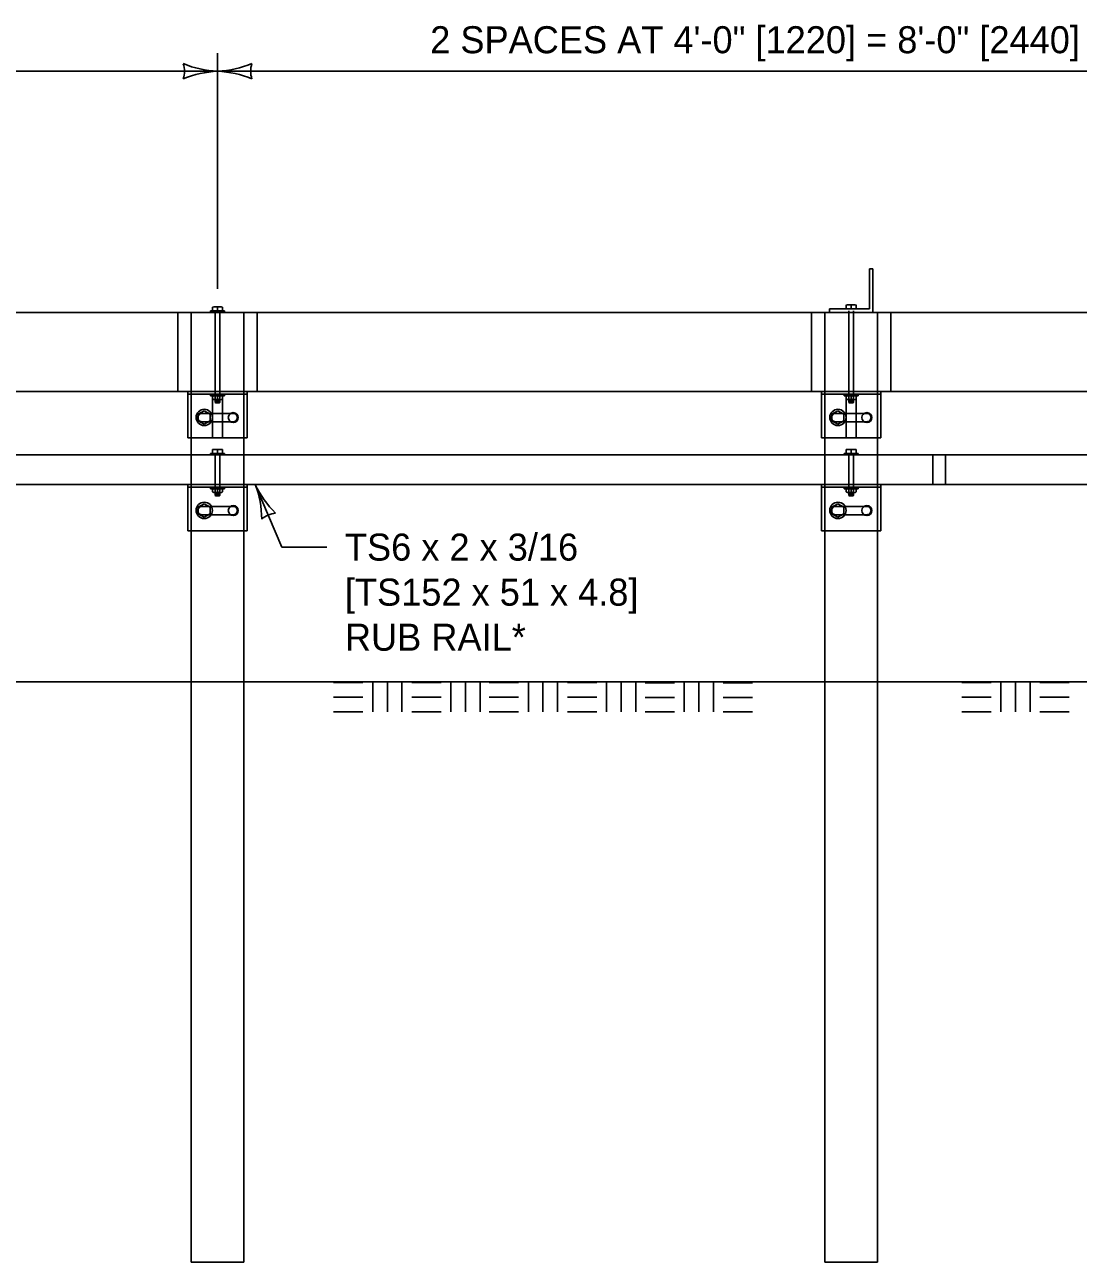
# Model space of a CAD drawing. Extents: x 49983 to 50021, y 49963.5 to 50011.4.
# Drawn here: x 50007.107 to 50009.444, y 49993.178 to 49995.925 of the extents above; entities that cross this region are included whole.
import ezdxf

# ---------------------------------------------------------------- set-up
doc = ezdxf.new("R2010")
doc.units = 0
for name, color, linetype in [('Level 1', 7, 'Continuous'), ('Level 10', 7, 'Continuous'), ('Level 2', 7, 'Continuous'), ('Level 3', 7, 'Continuous'), ('Level 4', 7, 'Continuous')]:
    doc.layers.add(name, color=color, linetype=linetype)

msp = doc.modelspace()

# ---------------------------------------------------------------- linework, layer by layer
at = {"layer": 'Level 1'}
for p, q in [((50008.9809, 49995.2944), (50008.9809, 49995.3826)), ((50008.9809, 49995.3826), (50008.9888, 49995.3826)), ((50008.9888, 49995.3826), (50008.9888, 49995.2862)), ((50008.9296, 49995.3027), (50008.9296, 49995.2944)), ((50008.9351, 49995.3033), (50008.9461, 49995.3033)), ((50008.9406, 49995.3027), (50008.9406, 49995.2944)), ((50008.9516, 49995.3027), (50008.9516, 49995.2944)), ((50013.5013, 49995.2862), (50005.468, 49995.2862)), ((50007.4765, 49995.2862), (50007.6522, 49995.2862)), ((50007.622, 49995.2862), (50007.5067, 49995.2862)), ((50007.5193, 49995.2899), (50007.5506, 49995.2899)), ((50007.5193, 49995.2899), (50007.5193, 49995.2862)), ((50007.524, 49995.2981), (50007.524, 49995.2899)), ((50007.5295, 49995.2988), (50007.5405, 49995.2988)), ((50007.535, 49995.2981), (50007.535, 49995.2899)), ((50007.5461, 49995.2981), (50007.5461, 49995.2899)), ((50007.5506, 49995.2899), (50007.5506, 49995.2862)), ((50008.882, 49995.2862), (50009.0577, 49995.2862)), ((50008.8924, 49995.2865), (50008.8924, 49995.2944)), ((50008.8924, 49995.2944), (50008.9809, 49995.2944)), ((50009.0275, 49995.2862), (50008.9123, 49995.2862)), ((50013.5013, 49995.1105), (50005.468, 49995.1105)), ((50007.4692, 49995.008), (50007.4692, 49995.1105)), ((50007.4765, 49995.1105), (50007.6522, 49995.1105)), ((50007.5204, 49995.1105), (50007.6522, 49995.1105)), ((50007.6009, 49995.008), (50007.6009, 49995.1105)), ((50008.8747, 49995.008), (50008.8747, 49995.1105)), ((50008.882, 49995.1105), (50009.0577, 49995.1105)), ((50008.926, 49995.1105), (50009.0577, 49995.1105)), ((50009.0065, 49995.008), (50009.0065, 49995.1105)), ((50007.6009, 49995.105), (50007.4692, 49995.105)), ((50007.5193, 49995.1014), (50007.5193, 49995.1051)), ((50007.5193, 49995.1014), (50007.5507, 49995.1014)), ((50007.524, 49995.0942), (50007.524, 49995.0997)), ((50007.5241, 49995.1014), (50007.5241, 49995.0998)), ((50007.5241, 49995.008), (50007.5241, 49995.0941)), ((50007.5295, 49995.0925), (50007.5406, 49995.0925)), ((50007.5299, 49995.0864), (50007.5299, 49995.0925)), ((50007.5402, 49995.0864), (50007.5299, 49995.0864)), ((50007.5299, 49995.0864), (50007.531, 49995.0853)), ((50007.531, 49995.0853), (50007.5392, 49995.0853)), ((50007.5314, 49995.091), (50007.5387, 49995.091)), ((50007.5314, 49995.09), (50007.5387, 49995.09)), ((50007.5314, 49995.089), (50007.5387, 49995.089)), ((50007.5314, 49995.0879), (50007.5387, 49995.0879)), ((50007.5351, 49995.0997), (50007.5351, 49995.0942)), ((50007.5402, 49995.0864), (50007.5392, 49995.0853)), ((50007.5402, 49995.0864), (50007.5402, 49995.0925)), ((50007.546, 49995.1014), (50007.546, 49995.0998)), ((50007.546, 49995.008), (50007.546, 49995.0941)), ((50007.5462, 49995.0942), (50007.5462, 49995.0997)), ((50007.5507, 49995.1014), (50007.5507, 49995.1051)), ((50009.0065, 49995.105), (50008.8747, 49995.105)), ((50008.9248, 49995.1014), (50008.9248, 49995.1051)), ((50008.9248, 49995.1014), (50008.9562, 49995.1014)), ((50008.9295, 49995.0942), (50008.9295, 49995.0997)), ((50008.9296, 49995.1014), (50008.9296, 49995.0998)), ((50008.9296, 49995.008), (50008.9296, 49995.0941)), ((50008.9351, 49995.0925), (50008.9462, 49995.0925)), ((50008.9355, 49995.0864), (50008.9355, 49995.0925)), ((50008.9458, 49995.0864), (50008.9355, 49995.0864)), ((50008.9355, 49995.0864), (50008.9365, 49995.0853)), ((50008.9365, 49995.0853), (50008.9447, 49995.0853)), ((50008.937, 49995.091), (50008.9442, 49995.091)), ((50008.937, 49995.09), (50008.9442, 49995.09)), ((50008.937, 49995.089), (50008.9442, 49995.089)), ((50008.937, 49995.0879), (50008.9442, 49995.0879)), ((50008.9406, 49995.0997), (50008.9406, 49995.0942)), ((50008.9458, 49995.0864), (50008.9447, 49995.0853)), ((50008.9458, 49995.0864), (50008.9458, 49995.0925)), ((50008.9516, 49995.1014), (50008.9516, 49995.0998)), ((50008.9516, 49995.008), (50008.9516, 49995.0941)), ((50008.9517, 49995.0942), (50008.9517, 49995.0997)), ((50008.9562, 49995.1014), (50008.9562, 49995.1051)), ((50007.5055, 49995.0678), (50007.4923, 49995.0601)), ((50007.4923, 49995.0601), (50007.4923, 49995.0453)), ((50007.5186, 49995.0601), (50007.5055, 49995.0678)), ((50007.5186, 49995.0453), (50007.5186, 49995.0601)), ((50007.5214, 49995.062), (50007.5241, 49995.062)), ((50007.546, 49995.062), (50007.5693, 49995.062)), ((50008.911, 49995.0678), (50008.8979, 49995.0601)), ((50008.8979, 49995.0601), (50008.8979, 49995.0453)), ((50008.9241, 49995.0601), (50008.911, 49995.0678)), ((50008.9241, 49995.0453), (50008.9241, 49995.0601)), ((50008.9269, 49995.062), (50008.9296, 49995.062)), ((50008.9516, 49995.062), (50008.9749, 49995.062)), ((50007.4923, 49995.0453), (50007.5055, 49995.0382)), ((50007.5055, 49995.0382), (50007.5186, 49995.0453)), ((50007.521, 49995.0437), (50007.5241, 49995.0437)), ((50007.546, 49995.0437), (50007.5698, 49995.0437)), ((50008.8979, 49995.0453), (50008.911, 49995.0382)), ((50008.911, 49995.0382), (50008.9241, 49995.0453)), ((50008.9266, 49995.0437), (50008.9296, 49995.0437)), ((50008.9516, 49995.0437), (50008.9754, 49995.0437)), ((50007.6009, 49995.008), (50007.4692, 49995.008)), ((50007.4763, 49995.008), (50007.4763, 49994.9698)), ((50007.5935, 49995.008), (50007.5935, 49994.9698)), ((50009.0065, 49995.008), (50008.8747, 49995.008)), ((50008.8819, 49995.008), (50008.8819, 49994.9698)), ((50008.999, 49995.008), (50008.999, 49994.9698)), ((50007.5193, 49994.9734), (50007.5506, 49994.9734)), ((50007.5193, 49994.9734), (50007.5193, 49994.9698)), ((50007.524, 49994.9817), (50007.524, 49994.9734)), ((50007.5295, 49994.9823), (50007.5405, 49994.9823)), ((50007.535, 49994.9817), (50007.535, 49994.9734)), ((50007.5461, 49994.9817), (50007.5461, 49994.9734)), ((50007.5506, 49994.9734), (50007.5506, 49994.9698)), ((50008.9249, 49994.9734), (50008.9561, 49994.9734)), ((50008.9249, 49994.9734), (50008.9249, 49994.9698)), ((50008.9296, 49994.9817), (50008.9296, 49994.9734)), ((50008.9351, 49994.9823), (50008.9461, 49994.9823)), ((50008.9406, 49994.9817), (50008.9406, 49994.9734)), ((50008.9516, 49994.9817), (50008.9516, 49994.9734)), ((50008.9561, 49994.9734), (50008.9561, 49994.9698)), ((50010.2874, 49994.9698), (50004.5699, 49994.9698)), ((50009.1498, 49994.9698), (50009.1498, 49994.9041)), ((50010.287, 49994.9041), (50005.1444, 49994.9041)), ((50007.4692, 49994.8016), (50007.4692, 49994.9041)), ((50007.6009, 49994.8986), (50007.4692, 49994.8986)), ((50007.6516, 49994.9041), (50007.4759, 49994.9041)), ((50007.5193, 49994.8949), (50007.5193, 49994.8986)), ((50007.5193, 49994.8949), (50007.5507, 49994.8949)), ((50007.5199, 49994.9041), (50007.6516, 49994.9041)), ((50007.524, 49994.8876), (50007.524, 49994.8932)), ((50007.5351, 49994.8932), (50007.5351, 49994.8876)), ((50007.5462, 49994.8876), (50007.5462, 49994.8932)), ((50007.5507, 49994.8949), (50007.5507, 49994.8986)), ((50007.6009, 49994.8016), (50007.6009, 49994.9041)), ((50008.8747, 49994.8016), (50008.8747, 49994.9041)), ((50009.0065, 49994.8986), (50008.8747, 49994.8986)), ((50009.0572, 49994.9041), (50008.8815, 49994.9041)), ((50008.9248, 49994.8949), (50008.9248, 49994.8986)), ((50008.9248, 49994.8949), (50008.9562, 49994.8949)), ((50008.9254, 49994.9041), (50009.0572, 49994.9041)), ((50008.9295, 49994.8876), (50008.9295, 49994.8932)), ((50008.9406, 49994.8932), (50008.9406, 49994.8876)), ((50008.9517, 49994.8876), (50008.9517, 49994.8932)), ((50008.9562, 49994.8949), (50008.9562, 49994.8986)), ((50009.0065, 49994.8016), (50009.0065, 49994.9041)), ((50007.5295, 49994.8859), (50007.5406, 49994.8859)), ((50007.5299, 49994.8798), (50007.5299, 49994.8859)), ((50007.5402, 49994.8798), (50007.5299, 49994.8798)), ((50007.5299, 49994.8798), (50007.531, 49994.8788)), ((50007.531, 49994.8788), (50007.5392, 49994.8788)), ((50007.5314, 49994.8845), (50007.5387, 49994.8845)), ((50007.5314, 49994.8835), (50007.5387, 49994.8835)), ((50007.5314, 49994.8824), (50007.5387, 49994.8824)), ((50007.5314, 49994.8814), (50007.5387, 49994.8814)), ((50007.5402, 49994.8798), (50007.5392, 49994.8788)), ((50007.5402, 49994.8798), (50007.5402, 49994.8859)), ((50008.9351, 49994.8859), (50008.9462, 49994.8859)), ((50008.9355, 49994.8798), (50008.9355, 49994.8859)), ((50008.9458, 49994.8798), (50008.9355, 49994.8798)), ((50008.9355, 49994.8798), (50008.9365, 49994.8788)), ((50008.9365, 49994.8788), (50008.9447, 49994.8788)), ((50008.937, 49994.8845), (50008.9442, 49994.8845)), ((50008.937, 49994.8835), (50008.9442, 49994.8835)), ((50008.937, 49994.8824), (50008.9442, 49994.8824)), ((50008.937, 49994.8814), (50008.9442, 49994.8814)), ((50008.9458, 49994.8798), (50008.9447, 49994.8788)), ((50008.9458, 49994.8798), (50008.9458, 49994.8859)), ((50007.5055, 49994.8613), (50007.4923, 49994.8537)), ((50007.4923, 49994.8537), (50007.4923, 49994.8389)), ((50007.4923, 49994.8389), (50007.5055, 49994.8318)), ((50007.5186, 49994.8537), (50007.5055, 49994.8613)), ((50007.5055, 49994.8318), (50007.5186, 49994.8389)), ((50007.5186, 49994.8389), (50007.5186, 49994.8537)), ((50007.521, 49994.8372), (50007.5698, 49994.8372)), ((50007.5214, 49994.8555), (50007.5693, 49994.8555)), ((50008.911, 49994.8613), (50008.8979, 49994.8537)), ((50008.8979, 49994.8537), (50008.8979, 49994.8389)), ((50008.8979, 49994.8389), (50008.911, 49994.8318)), ((50008.9241, 49994.8537), (50008.911, 49994.8613)), ((50008.911, 49994.8318), (50008.9241, 49994.8389)), ((50008.9241, 49994.8389), (50008.9241, 49994.8537)), ((50008.9266, 49994.8372), (50008.9754, 49994.8372)), ((50008.9269, 49994.8555), (50008.9749, 49994.8555)), ((50007.6009, 49994.8016), (50007.4692, 49994.8016)), ((50007.4763, 49994.8016), (50007.4763, 49994.4663)), ((50007.5935, 49994.8016), (50007.5935, 49994.4663)), ((50009.0065, 49994.8016), (50008.8747, 49994.8016)), ((50008.8819, 49994.8016), (50008.8819, 49994.4663)), ((50008.999, 49994.8016), (50008.999, 49994.4663)), ((50015.1755, 49994.4663), (50005.1046, 49994.4663)), ((50007.7924, 49994.4646), (50007.8574, 49994.4646)), ((50007.8791, 49994.3996), (50007.8791, 49994.4646)), ((50007.9116, 49994.3996), (50007.9116, 49994.4646)), ((50007.9441, 49994.3996), (50007.9441, 49994.4646)), ((50007.9657, 49994.4646), (50008.0308, 49994.4646)), ((50008.0525, 49994.3996), (50008.0525, 49994.4646)), ((50008.0849, 49994.3996), (50008.0849, 49994.4646)), ((50008.1174, 49994.3996), (50008.1174, 49994.4646)), ((50008.1377, 49994.4645), (50008.2027, 49994.4645)), ((50008.2244, 49994.3995), (50008.2244, 49994.4645)), ((50008.2569, 49994.3995), (50008.2569, 49994.4645)), ((50008.2894, 49994.3995), (50008.2894, 49994.4645)), ((50008.311, 49994.4645), (50008.3761, 49994.4645)), ((50008.3978, 49994.3995), (50008.3978, 49994.4645)), ((50008.4302, 49994.3995), (50008.4302, 49994.4645)), ((50008.4627, 49994.3995), (50008.4627, 49994.4645)), ((50008.4833, 49994.4643), (50008.5483, 49994.4643)), ((50008.57, 49994.3993), (50008.57, 49994.4643)), ((50008.6025, 49994.3993), (50008.6025, 49994.4643)), ((50008.635, 49994.3993), (50008.635, 49994.4643)), ((50008.6566, 49994.4643), (50008.7217, 49994.4643)), ((50009.186, 49994.4646), (50009.251, 49994.4646)), ((50009.2727, 49994.3996), (50009.2727, 49994.4646)), ((50009.3052, 49994.3996), (50009.3052, 49994.4646)), ((50009.3377, 49994.3996), (50009.3377, 49994.4646)), ((50009.3593, 49994.4646), (50009.4244, 49994.4646)), ((50007.7924, 49994.4321), (50007.8574, 49994.4321)), ((50007.9657, 49994.4321), (50008.0308, 49994.4321)), ((50008.1377, 49994.432), (50008.2027, 49994.432)), ((50008.311, 49994.432), (50008.3761, 49994.432)), ((50008.4833, 49994.4318), (50008.5483, 49994.4318)), ((50008.6566, 49994.4318), (50008.7217, 49994.4318)), ((50009.186, 49994.4321), (50009.251, 49994.4321)), ((50009.3593, 49994.4321), (50009.4244, 49994.4321)), ((50007.7924, 49994.3996), (50007.8574, 49994.3996)), ((50007.9657, 49994.3996), (50008.0308, 49994.3996)), ((50008.1377, 49994.3995), (50008.2027, 49994.3995)), ((50008.311, 49994.3995), (50008.3761, 49994.3995)), ((50008.4833, 49994.3993), (50008.5483, 49994.3993)), ((50008.6566, 49994.3993), (50008.7217, 49994.3993)), ((50009.186, 49994.3996), (50009.251, 49994.3996)), ((50009.3593, 49994.3996), (50009.4244, 49994.3996))]:
    msp.add_line(p, q, dxfattribs=at)
for centre in [(50007.5056, 49995.0531), (50008.9111, 49995.0531), (50007.5056, 49994.8467), (50008.9111, 49994.8467)]:
    msp.add_circle(centre, 0.0181, dxfattribs=at)
for centre, radius, start, end in [((50008.9351, 49995.2802), 0.0231, 76.2307, 103.7693), ((50008.9461, 49995.2802), 0.0231, 76.2307, 103.7693), ((50007.5295, 49995.2757), 0.0231, 76.2307, 103.7693), ((50007.5405, 49995.2757), 0.0231, 76.2307, 103.7693), ((50007.5295, 49995.0916), 0.00981, 55.616, 124.384), ((50007.5295, 49995.1023), 0.00981, 235.616, 304.384), ((50007.5406, 49995.0916), 0.00981, 55.616, 124.384), ((50007.5406, 49995.1023), 0.00981, 235.616, 304.384), ((50008.9351, 49995.0916), 0.00981, 55.616, 124.384), ((50008.9351, 49995.1023), 0.00981, 235.616, 304.384), ((50008.9462, 49995.0916), 0.00981, 55.616, 124.384), ((50008.9462, 49995.1023), 0.00981, 235.616, 304.384), ((50007.5698, 49995.0528), 0.00916, 270, 93.2408), ((50008.9754, 49995.0528), 0.00916, 270, 93.2408), ((50007.5295, 49994.9592), 0.0231, 76.2307, 103.7693), ((50007.5405, 49994.9592), 0.0231, 76.2307, 103.7693), ((50008.9351, 49994.9592), 0.0231, 76.2307, 103.7693), ((50008.9461, 49994.9592), 0.0231, 76.2307, 103.7693), ((50007.5295, 49994.8851), 0.00981, 55.616, 124.384), ((50007.5406, 49994.8851), 0.00981, 55.616, 124.384), ((50008.9351, 49994.8851), 0.00981, 55.616, 124.384), ((50008.9462, 49994.8851), 0.00981, 55.616, 124.384), ((50007.5295, 49994.8957), 0.00981, 235.616, 304.384), ((50007.5406, 49994.8957), 0.00981, 235.616, 304.384), ((50008.9351, 49994.8957), 0.00981, 235.616, 304.384), ((50008.9462, 49994.8957), 0.00981, 235.616, 304.384), ((50007.5698, 49994.8464), 0.00916, 270, 93.2408), ((50008.9754, 49994.8464), 0.00916, 270, 93.2408)]:
    msp.add_arc(centre, radius, start, end, dxfattribs=at)
at = {"layer": 'Level 10'}
for p, q in [((50007.4763, 49995.008), (50007.4763, 49995.2862)), ((50007.5299, 49995.2899), (50007.5299, 49995.0925)), ((50007.5401, 49995.2899), (50007.5401, 49995.0925)), ((50007.5935, 49995.008), (50007.5935, 49995.2862)), ((50008.8819, 49995.008), (50008.8819, 49995.2862)), ((50008.9355, 49995.2899), (50008.9355, 49995.0925)), ((50008.9457, 49995.2899), (50008.9457, 49995.0925)), ((50008.999, 49995.008), (50008.999, 49995.2862)), ((50007.5241, 49995.1014), (50007.5241, 49995.105)), ((50007.546, 49995.1014), (50007.546, 49995.105)), ((50008.9296, 49995.1014), (50008.9296, 49995.105)), ((50008.9516, 49995.1014), (50008.9516, 49995.105)), ((50007.5008, 49995.062), (50007.5214, 49995.062)), ((50007.546, 49995.062), (50007.5241, 49995.062)), ((50008.9063, 49995.062), (50008.9269, 49995.062)), ((50008.9516, 49995.062), (50008.9296, 49995.062)), ((50007.5003, 49995.0437), (50007.521, 49995.0437)), ((50007.546, 49995.0437), (50007.5241, 49995.0437)), ((50008.9058, 49995.0437), (50008.9266, 49995.0437)), ((50008.9516, 49995.0437), (50008.9296, 49995.0437)), ((50007.5299, 49994.9734), (50007.5299, 49994.8859)), ((50007.5401, 49994.9734), (50007.5401, 49994.8859)), ((50008.9355, 49994.9734), (50008.9355, 49994.8859)), ((50008.9457, 49994.9734), (50008.9457, 49994.8859)), ((50007.4763, 49994.9698), (50007.4763, 49994.8016)), ((50007.5935, 49994.9698), (50007.5935, 49994.8016)), ((50008.8819, 49994.9698), (50008.8819, 49994.8016)), ((50008.999, 49994.9698), (50008.999, 49994.8016)), ((50009.122, 49994.9698), (50009.122, 49994.9041)), ((50007.5003, 49994.8372), (50007.521, 49994.8372)), ((50007.5008, 49994.8555), (50007.5214, 49994.8555)), ((50008.9058, 49994.8372), (50008.9266, 49994.8372)), ((50008.9063, 49994.8555), (50008.9269, 49994.8555))]:
    msp.add_line(p, q, dxfattribs=at)
for centre in [(50007.5698, 49995.0528), (50008.9754, 49995.0528), (50007.5698, 49994.8464), (50008.9754, 49994.8464)]:
    msp.add_circle(centre, 0.011, dxfattribs=at)
for centre in [(50007.5003, 49995.0528), (50008.9058, 49995.0528), (50007.5003, 49994.8464), (50008.9058, 49994.8464)]:
    msp.add_arc(centre, 0.00916, 86.7592, 270, dxfattribs=at)
at = {"layer": 'Level 3'}
for p, q in [((50007.535, 49995.3388), (50007.535, 49995.8615)), ((50005.4304, 49995.8215), (50007.535, 49995.8215)), ((50007.535, 49995.8215), (50010.3461, 49995.8215)), ((50007.6187, 49994.9041), (50007.6775, 49994.7653)), ((50007.6775, 49994.7653), (50007.7775, 49994.7653))]:
    msp.add_line(p, q, dxfattribs=at)
for centre, radius, start, end in [((50007.5442, 49996.0437), 0.2223, 247.456, 267.6395), ((50007.4068, 49995.8215), 0.0548, 342.1388, 17.8612), ((50007.5236, 49996.0543), 0.233, 272.8273, 292.0772), ((50007.6633, 49995.8215), 0.0548, 162.1388, 197.8612), ((50007.5465, 49995.5888), 0.233, 92.8273, 112.0772), ((50007.5259, 49995.5994), 0.2223, 67.456, 87.6395), ((50007.4106, 49994.8259), 0.2223, 0.3999, 20.5834), ((50007.8285, 49995.0054), 0.233, 205.7712, 225.0211), ((50007.6687, 49994.786), 0.0548, 95.0827, 130.8051)]:
    msp.add_arc(centre, radius, start, end, dxfattribs=at)
at = {"layer": 'Level 4'}
for p, q in [((50007.4472, 49995.2862), (50007.4472, 49995.1105)), ((50007.6229, 49995.2862), (50007.6229, 49995.1105)), ((50008.8527, 49995.2862), (50008.8527, 49995.1105)), ((50009.0284, 49995.2862), (50009.0284, 49995.1105)), ((50007.4763, 49993.1779), (50007.4763, 49994.4663)), ((50007.5935, 49994.4663), (50007.5935, 49993.1779)), ((50008.8819, 49993.1779), (50008.8819, 49994.4663)), ((50008.999, 49994.4663), (50008.999, 49993.1779)), ((50007.5935, 49993.1779), (50007.4763, 49993.1779)), ((50008.999, 49993.1779), (50008.8819, 49993.1779))]:
    msp.add_line(p, q, dxfattribs=at)

# ---------------------------------------------------------------- texts
at = {"layer": 'Level 2'}
for s, p in [('2 SPACES AT 4\'-0" [1220] = 8\'-0" [2440]', (50008.0067, 49995.8615)), ('TS6 x 2 x 3/16', (50007.8175, 49994.7353)), ('[TS152 x 51 x 4.8]', (50007.8175, 49994.6353)), ('RUB RAIL*', (50007.8175, 49994.5353))]:
    msp.add_text(s, height=0.06, dxfattribs=at).set_placement(p)

doc.saveas('drawing.dxf')
